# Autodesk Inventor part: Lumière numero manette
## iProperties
Created: 2010-07
Part Number: Lumière numero manette
Document SubType Name: Modeling
Designer: eric
Density: 1 g/cm^3
Author: eric
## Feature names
1. Base1
